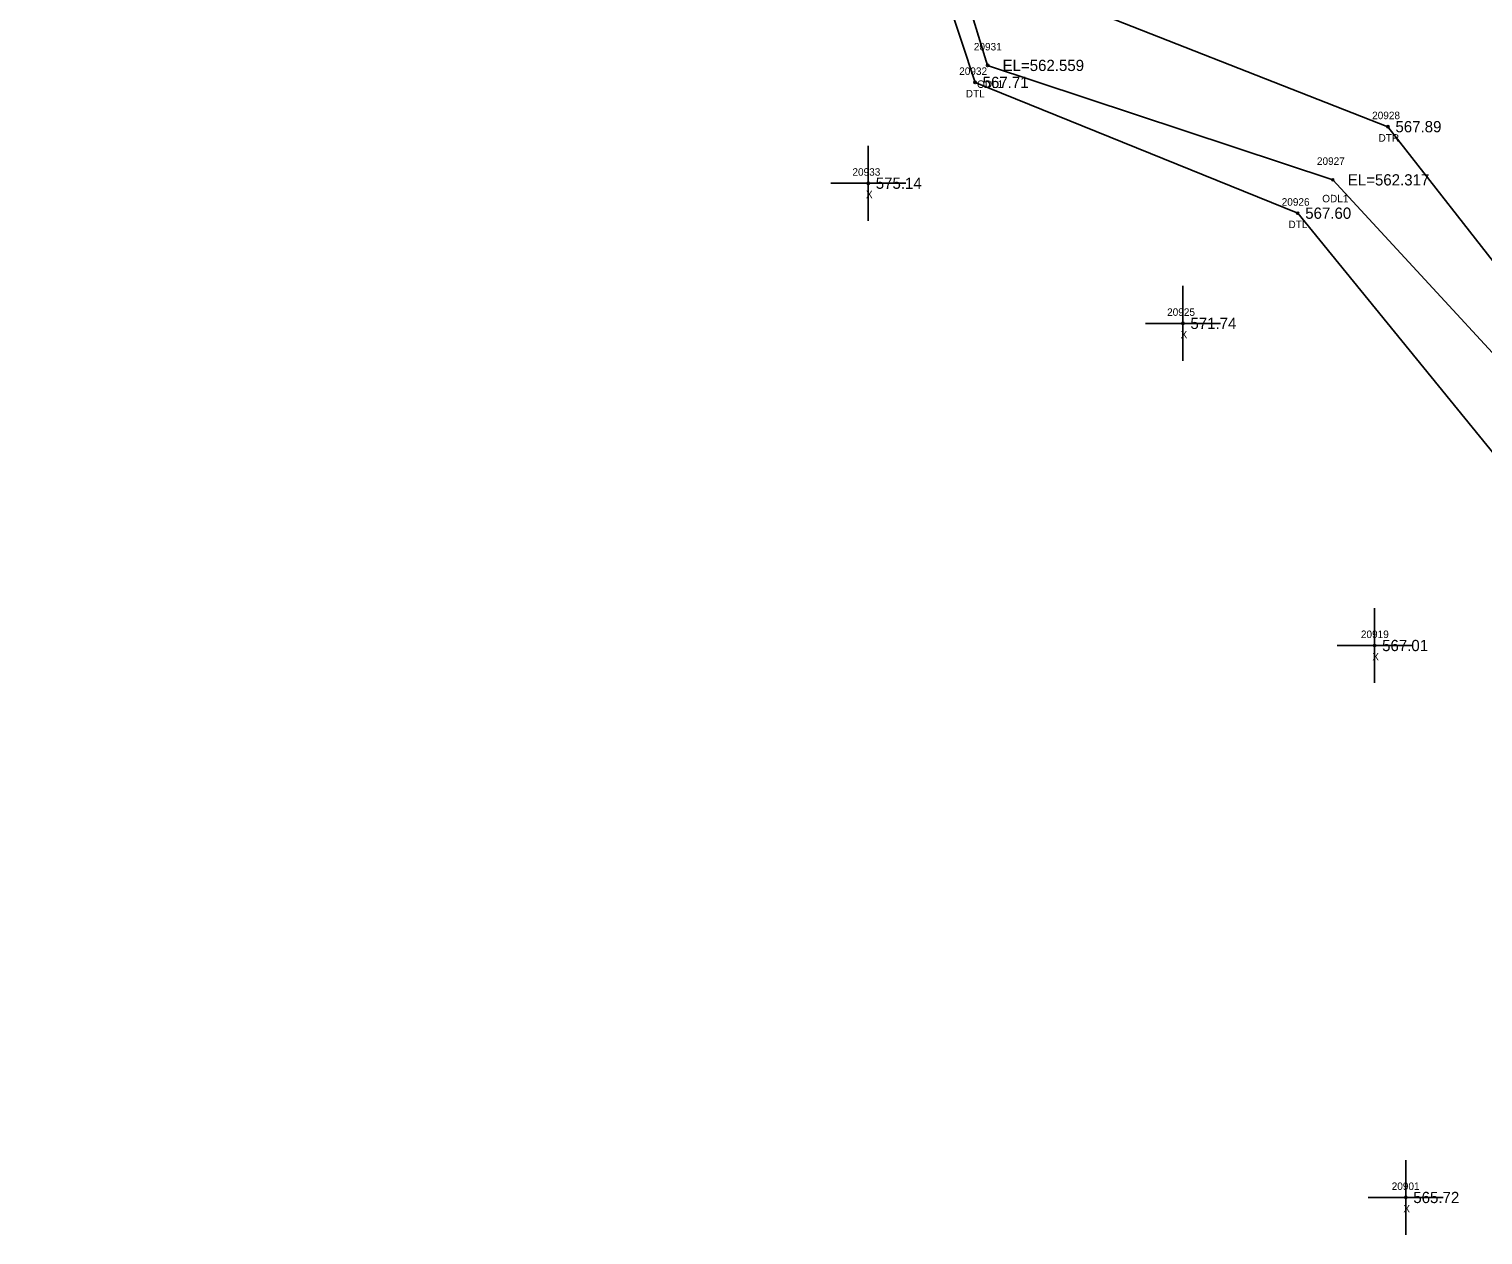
# Model space of a CAD drawing. Extents: x 1695443 to 1696344, y 1087542 to 1090645.
# Drawn here: x 1695474.5 to 1695668.5, y 1088954.6 to 1089115.6 of the extents above; entities that cross this region are included whole.
import ezdxf

# ---------------------------------------------------------------- set-up
doc = ezdxf.new("R2010")
doc.units = 0
for name, color, linetype in [('RD_EX_H2O', 7, 'Continuous'), ('RD_EX_H2O_txCode', 7, 'Continuous'), ('RD_EX_Misc', 7, 'Continuous'), ('RD_EX_Misc_txCode', 7, 'Continuous'), ('RD_EX_TX_H2O_ELEV', 7, 'Continuous'), ('RD_EX_TX_Misc_ELEV', 7, 'Continuous'), ('RD_SMD_Locator', 7, 'Continuous')]:
    doc.layers.add(name, color=color, linetype=linetype)

msp = doc.modelspace()

# ---------------------------------------------------------------- linework, layer by layer
at = {"layer": 'RD_EX_H2O'}
for points in [[(1695741.44, 1088979.77), (1695735.36, 1088982.13), (1695733.74, 1089010.53), (1695714.12, 1089041.46), (1695688.87, 1089060.37), (1695655.87, 1089102.57), (1695608.91, 1089121.01), (1695600.2, 1089162.09), (1695581.57, 1089225.22), (1695514.41, 1089303.03), (1695500.66, 1089306.61), (1695490.41, 1089302.07), (1695489.34, 1089311.94), (1695498.55, 1089320.55), (1695495.21, 1089339.52)], [(1695727.71, 1088968.15), (1695711.81, 1088974.31), (1695709.85, 1089000.95), (1695713.57, 1089012.1), (1695692.24, 1089031.37), (1695674.55, 1089053.33), (1695643.83, 1089091.02), (1695600.78, 1089108.48), (1695586.08, 1089153.06), (1695562.04, 1089227.51), (1695501.97, 1089294.68), (1695480.62, 1089297.16), (1695479.18, 1089314.76), (1695479.78, 1089327.68), (1695474.54, 1089335.41)], [(1695742.91, 1088967.28), (1695718.08, 1088980.23), (1695718.13, 1089011.92), (1695699.88, 1089034.17), (1695684.21, 1089056.74), (1695648.51, 1089095.47), (1695602.44, 1089110.75), (1695589.22, 1089153.92), (1695564.5, 1089229.98), (1695504.85, 1089296.49), (1695485.1, 1089301.93), (1695482.27, 1089302.79), (1695487.67, 1089314.21), (1695485.89, 1089334.31)]]:
    msp.add_lwpolyline(points, dxfattribs=at)
at = {"layer": 'RD_EX_Misc'}
for p, q in [((1695586.52, 1089090.02), (1695586.52, 1089100.02)), ((1695581.52, 1089095.02), (1695591.52, 1089095.02)), ((1695628.51, 1089071.31), (1695628.51, 1089081.31)), ((1695623.51, 1089076.31), (1695633.51, 1089076.31)), ((1695654.09, 1089028.3), (1695654.09, 1089038.3)), ((1695649.09, 1089033.3), (1695659.09, 1089033.3)), ((1695658.25, 1088954.61), (1695658.25, 1088964.61)), ((1695653.25, 1088959.61), (1695663.25, 1088959.61))]:
    msp.add_line(p, q, dxfattribs=at)
at = {"layer": 'RD_SMD_Locator'}
for centre in [(1695602.44, 1089110.75), (1695600.78, 1089108.48), (1695655.87, 1089102.57), (1695586.52, 1089095.02), (1695648.51, 1089095.47), (1695643.83, 1089091.02), (1695628.51, 1089076.31), (1695654.09, 1089033.3), (1695658.25, 1088959.61)]:
    msp.add_circle(centre, 0.15, dxfattribs=at)

# ---------------------------------------------------------------- texts
at = {"layer": 'RD_EX_H2O_txCode'}
for s, p in [('20931', (1695600.61, 1089112.75)), ('20932', (1695598.66, 1089109.48)), ('ODL1', (1695601.03, 1089107.75)), ('DTL', (1695599.53, 1089106.48)), ('20928', (1695653.76, 1089103.57)), ('DTR', (1695654.61, 1089100.57)), ('20927', (1695646.39, 1089097.47)), ('20926', (1695641.69, 1089092.02)), ('ODL1', (1695647.1, 1089092.47)), ('DTL', (1695642.59, 1089089.02))]:
    msp.add_text(s, height=1, dxfattribs=at).set_placement(p)
at = {"layer": 'RD_EX_Misc_txCode'}
for s, p in [('20933', (1695584.41, 1089096.02)), ('X', (1695586.21, 1089093.02)), ('20925', (1695626.4, 1089077.31)), ('X', (1695628.2, 1089074.31)), ('20919', (1695652.26, 1089034.3)), ('X', (1695653.78, 1089031.3)), ('20901', (1695656.37, 1088960.61)), ('X', (1695657.93, 1088957.61))]:
    msp.add_text(s, height=1, dxfattribs=at).set_placement(p)
at = {"layer": 'RD_EX_TX_H2O_ELEV'}
for s, p in [('EL=562.559', (1695604.44, 1089110)), ('567.71', (1695601.78, 1089107.73)), ('567.89', (1695656.87, 1089101.82)), ('EL=562.317', (1695650.51, 1089094.72)), ('567.60', (1695644.83, 1089090.27))]:
    msp.add_text(s, height=1.5, dxfattribs=at).set_placement(p)
at = {"layer": 'RD_EX_TX_Misc_ELEV'}
for s, p in [('575.14', (1695587.52, 1089094.27)), ('571.74', (1695629.51, 1089075.56)), ('567.01', (1695655.09, 1089032.55)), ('565.72', (1695659.25, 1088958.86))]:
    msp.add_text(s, height=1.5, dxfattribs=at).set_placement(p)

doc.saveas('drawing.dxf')
